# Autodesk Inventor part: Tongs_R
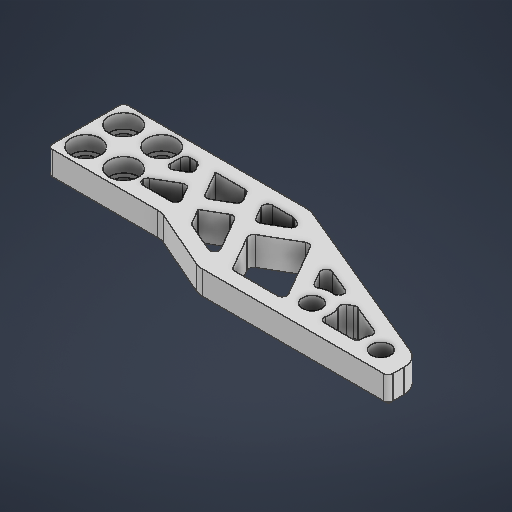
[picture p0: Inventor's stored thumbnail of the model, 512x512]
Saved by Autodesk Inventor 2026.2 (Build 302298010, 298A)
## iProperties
Created: 2026-05
Part Number: Tongs_R
Material: 일반
Document SubType Name: Modeling
Designer: work
Density: 1 g/cm^3
Appearance: 기본값
Author: work
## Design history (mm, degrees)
sketch "스케치1"
  geometry: L1 (-4, 4)-(4, 4); L2 (4, 4)-(4, -4); L3 (4, -4)-(-4, -4); L4 (-4, -4)-(-4, 4); L5 (-4, 4)-(4, -4); L6 (4, 4)-(-4, -4); L7 (-8, 8)-(8, 8); L8 (8, 8)-(8, -8); L9 (8, -8)-(-8, -8); L10 (-8, -8)-(-8, 8); L11 (-8, 8)-(8, -8); L12 (8, 8)-(-8, -8); L13 (-8, 8)-(-16, 8); L14 (-16, 8)-(-29.748, 14); L15 (-29.748, 14)-(-69.748, 14); L16 (-69.748, 14)-(-69.748, 8); L17 (-69.748, 8)-(-31.398, -8); L18 (-31.398, -8)-(-8, -8); L19 (-8, -5)-(-30.797, -5); L20 (-30.797, -5)-(-66.748, 9.999); L21 (-66.748, 9.999)-(-66.748, 11); L22 (-66.748, 11)-(-30.374, 11); L23 (-30.374, 11)-(-16.626, 5); L24 (-16.626, 5)-(-8, 5); L25 (-48.561, 11)-(-42.029, -0.314); L26 (-45.097, 11)-(-37.465, -2.218); L27 (-30.374, 11)-(-21.136, -5); L28 (-33.838, 11)-(-24.6, -5); L29 (-16.626, 5)-(-10.853, -5); L30 (-21.257, 7.021)-(-14.317, -5); L31 (-37.465, -2.218)-(-29.021, 2.657); L32 (-27.521, 0.059)-(-33.982, -3.671); L33 (-13.739, 0)-(-8, 3.314); L34 (-12.239, -2.598)-(-8, -0.15); L35 (-17.787, 1.011)-(-22.902, -1.942); L36 (-24.402, 0.656)-(-19.287, 3.609); L37 (-46.029, 6.614)-(-51.317, 3.561); L38 (-47.029, 8.346)-(-53.639, 4.53); C1 r 2 at (4, 4); C2 r 2 at (4, -4); C3 r 2 at (-4, -4); C4 r 2 at (-4, 4); 4 further points
  constraints: 76 end point, 24 point on line, 19 parallel, 8 midpoint, 6 perpendicular, 4 centre point, 4 coincident, 3 horizontal, 5 other
  dimensions: "d0" = 8 distance of L2.end L3.end; "d1" = 8 distance of L1.end L2.end; "d2" = 4 diameter of C1; "d3" = 4 diameter of C2; "d4" = 4 diameter of C3; "d5" = 4 diameter of C4; "d6" = 4 distance between parallel lines of L8 L2; "d7" = 8 distance of L7.start L13.end; "d8" = 15 distance of L13.end L14.end; "d9" = 40 distance of L14.end L15.end; "d10" = 6 distance of L15.end L16.end; "d11" = 38.34957 horizontal distance of L16.end L17.end; "d12" = 3 distance between parallel lines of L14 L23; "d13" = 3 distance between parallel lines of L25 L26; "d14" = 3 distance between parallel lines of L28 L27; "d15" = 3 distance between parallel lines of L30 L29; "d16" = 120 deg angle of L22 L28; "d17" = 3 distance between parallel lines of L35 L36; "d18" = 3 distance from line of L31 point (-30.752, -1.806); "d19" = 2 distance between parallel lines of L38 L37; "d20" = 8 distance from line of L25.end L37; "d21" = 3 distance between parallel lines of L34 L33
extrude "돌출1" new body sketch "스케치1" distance "d22" = 6; taper "d23" = 0 deg
sketch "스케치2"
  geometry: L1 (16, -8)-(29.748, -14) reference; L2 (29.748, -14)-(69.748, -14) reference; L3 (69.748, -14)-(69.748, -8) reference; L4 (69.748, -8)-(31.398, 8) reference; L5 (31.398, 8)-(-8, 8) reference; L6 (-8, 8)-(-8, -8) reference; L7 (-8, -8)-(16, -8) reference; L8 (27.521, -0.059)-(24.6, 5) reference; L9 (24.6, 5)-(30.797, 5) reference; L10 (30.797, 5)-(33.982, 3.671) reference; L11 (33.982, 3.671)-(27.521, -0.059) reference; L12 (12.239, 2.598)-(8, 0.15) reference; L13 (8, 0.15)-(8, 5) reference; L14 (8, 5)-(10.853, 5) reference; L15 (10.853, 5)-(12.239, 2.598) reference; L16 (17.787, -1.011)-(14.317, 5) reference; L17 (14.317, 5)-(21.136, 5) reference; L18 (21.136, 5)-(22.902, 1.942) reference; L19 (22.902, 1.942)-(17.787, -1.011) reference; L20 (46.029, -6.614)-(42.029, 0.314) reference; L21 (42.029, 0.314)-(51.317, -3.561) reference; L22 (51.317, -3.561)-(46.029, -6.614) reference; L23 (13.739, 0)-(16.626, -5) reference; L24 (16.626, -5)-(8, -5) reference; L25 (8, -5)-(8, -3.314) reference; L26 (8, -3.314)-(13.739, 0) reference; L27 (19.287, -3.609)-(24.402, -0.656) reference; L28 (24.402, -0.656)-(30.374, -11) reference; L29 (30.374, -11)-(21.257, -7.021) reference; L30 (21.257, -7.021)-(19.287, -3.609) reference; L31 (29.021, -2.657)-(37.465, 2.218) reference; L32 (37.465, 2.218)-(45.097, -11) reference; L33 (45.097, -11)-(33.838, -11) reference; L34 (33.838, -11)-(29.021, -2.657) reference; L35 (47.029, -8.346)-(53.639, -4.53) reference; L36 (53.639, -4.53)-(66.748, -9.999) reference; L37 (66.748, -9.999)-(66.748, -11) reference; L38 (66.748, -11)-(48.561, -11) reference; L39 (48.561, -11)-(47.029, -8.346) reference; C1 r 2 at (4, -4) reference; C2 r 2 at (4, 4) reference; C3 r 2 at (-4, 4) reference; C4 r 2 at (-4, -4) reference; 5 further points
  constraints: 4 coincident
hole "구멍1" sketch "스케치2" at (-4, -4), (4, -4), (4, 4), (-4, 4) diameter "d24" = 4; stored, may be unused: countersink angle "d28" = 90 deg, drill point angle "d30" = 118 deg; dims "d25" = 6, "d26" = 6.2, "d27" = 3, "d29" = 8
fillet "모깎기1" dims "d31" = 1
fillet "모깎기2" dims "d32" = 4
fillet "모깎기3" dims "d33" = 1
chamfer "모따기1" distance "d34" = 1; stored, may be unused: second distance "d35" = 2, angle "d36" = 45 deg
node "작업 평면1"
sketch "스케치3"
  geometry: L1 (69.748, -13)-(69.748, -10.665) reference; L2 (67.288, -6.974)-(32.137, 7.692) reference; L3 (30.597, 8)-(-7, 8) reference; L4 (-8, 7)-(-8, -7) reference; L5 (-7, -8)-(15.165, -8) reference; L6 (16.765, -8.334)-(28.983, -13.666) reference; L7 (30.583, -14)-(68.748, -14) reference; L8 (27.021, 0.807)-(25.466, 3.5) reference; L9 (26.332, 5)-(30.597, 5) reference; L10 (30.982, 4.923)-(32.117, 4.45) reference; L11 (32.232, 2.661)-(28.387, 0.441) reference; L12 (11.373, 2.098)-(9.5, 1.016) reference; L13 (8, 1.883)-(8, 4) reference; L14 (9, 5)-(10.275, 5) reference; L15 (11.141, 4.5)-(11.739, 3.464) reference; L16 (17.287, -0.145)-(14.317, 5) reference; L17 (14.317, 5)-(20.559, 5) reference; L18 (21.425, 4.5)-(22.402, 2.808) reference; L19 (22.036, 1.442)-(18.653, -0.511) reference; L20 (45.529, -5.748)-(43.508, -2.248) reference; L21 (44.759, -0.825)-(49.451, -2.783) reference; L22 (49.566, -4.572)-(46.895, -6.114) reference; L23 (14.239, -0.866)-(15.76, -3.5) reference; L24 (14.894, -5)-(9, -5) reference; L25 (8, -4)-(8, -3.891) reference; L26 (8.5, -3.025)-(12.873, -0.5) reference; L27 (19.287, -3.609)-(23.536, -1.156) reference; L28 (24.902, -1.522)-(28.854, -8.368) reference; L29 (27.588, -9.784)-(21.559, -7.153) reference; L30 (21.093, -6.736)-(19.287, -3.609) reference; L31 (29.887, -2.157)-(36.599, 1.718) reference; L32 (37.965, 1.352)-(44.231, -9.5) reference; L33 (43.365, -11)-(34.415, -11) reference; L34 (33.549, -10.5)-(29.521, -3.523) reference; L35 (47.895, -7.846)-(53.21, -4.777) reference; L36 (54.095, -4.72)-(64.538, -9.077) reference; L37 (64.153, -11)-(49.138, -11) reference; L38 (48.272, -10.5)-(47.529, -9.212) reference; C1 r 3.1 at (-4, 4) reference; C2 r 3.1 at (4, 4) reference; C3 r 3.1 at (4, -4) reference; C4 r 3.1 at (-4, -4) reference; C5 r 4 at (64.153, -10); C6 r 2 at (64.153, -10); C7 r 4 at (48.395, -8.712); C8 r 2 at (48.395, -8.712); A1 r 1 centre (68.748, -13) between (68.748, -14) and (69.748, -13) reference; A2 r 4 centre (65.748, -10.665) between (69.748, -10.665) and (67.288, -6.974) reference; A3 r 4 centre (30.597, 4) between (32.137, 7.692) and (30.597, 8) reference; A4 r 1 centre (-7, 7) between (-7, 8) and (-8, 7) reference; A5 r 1 centre (-7, -7) between (-8, -7) and (-7, -8) reference; A6 r 4 centre (15.165, -12) between (16.765, -8.334) and (15.165, -8) reference; A7 r 4 centre (30.583, -10) between (28.983, -13.666) and (30.583, -14) reference; A8 r 1 centre (26.332, 4) between (26.332, 5) and (25.466, 3.5) reference; A9 r 1 centre (30.597, 4) between (30.982, 4.923) and (30.597, 5) reference; A10 r 1 centre (31.732, 3.527) between (32.232, 2.661) and (32.117, 4.45) reference; A11 r 1 centre (27.887, 1.307) between (27.021, 0.807) and (28.387, 0.441) reference; A12 r 1 centre (9, 1.883) between (8, 1.883) and (9.5, 1.016) reference; A13 r 1 centre (9, 4) between (9, 5) and (8, 4) reference; A14 r 1 centre (10.275, 4) between (11.141, 4.5) and (10.275, 5) reference; A15 r 1 centre (10.873, 2.964) between (11.373, 2.098) and (11.739, 3.464) reference; A16 r 1 centre (20.559, 4) between (21.425, 4.5) and (20.559, 5) reference; A17 r 1 centre (21.536, 2.308) between (22.036, 1.442) and (22.402, 2.808) reference; A18 r 1 centre (18.153, 0.355) between (17.287, -0.145) and (18.653, -0.511) reference; A19 r 1 centre (44.374, -1.748) between (44.759, -0.825) and (43.508, -2.248) reference; A20 r 1 centre (49.066, -3.706) between (49.566, -4.572) and (49.451, -2.783) reference; A21 r 1 centre (46.395, -5.248) between (45.529, -5.748) and (46.895, -6.114) reference; A22 r 1 centre (14.894, -4) between (14.894, -5) and (15.76, -3.5) reference; A23 r 1 centre (9, -4) between (8, -4) and (9, -5) reference; A24 r 1 centre (9, -3.891) between (8.5, -3.025) and (8, -3.891) reference; A25 r 1 centre (13.373, -1.366) between (14.239, -0.866) and (12.873, -0.5) reference; A26 r 1 centre (24.036, -2.022) between (24.902, -1.522) and (23.536, -1.156) reference; A27 r 1 centre (27.988, -8.868) between (27.588, -9.784) and (28.854, -8.368) reference; A28 r 1 centre (21.959, -6.236) between (21.093, -6.736) and (21.559, -7.153) reference; A29 r 1 centre (37.099, 0.852) between (37.965, 1.352) and (36.599, 1.718) reference; A30 r 1 centre (43.365, -10) between (43.365, -11) and (44.231, -9.5) reference; A31 r 1 centre (34.415, -10) between (33.549, -10.5) and (34.415, -11) reference; A32 r 1 centre (30.387, -3.023) between (29.887, -2.157) and (29.521, -3.523) reference; A33 r 1 centre (53.71, -5.643) between (54.095, -4.72) and (53.21, -4.777) reference; A34 r 1 centre (64.153, -10) between (64.153, -11) and (64.538, -9.077) reference; A35 r 1 centre (49.138, -10) between (48.272, -10.5) and (49.138, -11) reference; A36 r 1 centre (48.395, -8.712) between (47.895, -7.846) and (47.529, -9.212) reference; A37 r 1 centre (48.395, -8.712) between (47.895, -7.846) and (47.529, -9.212) reference; 11 further points
  constraints: 4 centre point, 4 coincident
  dimensions: "d38" = 8 diameter of C5; "d41" = 4 diameter of C6; "d42" = 8 diameter of C7; "d43" = 4 diameter of C8
  node "투영된 루프2"
extrude "돌출2" join sketch "스케치3" stored distance "d44" = 10; taper "d45" = 0 deg
extrude "돌출3" cut sketch "스케치3" extent not by distance; stored distance "d46" = 0; taper "d47" = 0 deg
fillet "모깎기4" dims "d48" = 1
node "솔리드1"
node "투영된 루프1"
feature "A9D066F2-1C7D-4E18-AEED-F7BC21143FA4" dims "d24" = 4, "d25" = 6, "d26" = 6.2, "d27" = 3, "d28" = 90 deg, "d29" = 8, "d30" = 118 deg
other parameters: "d37" = 0
